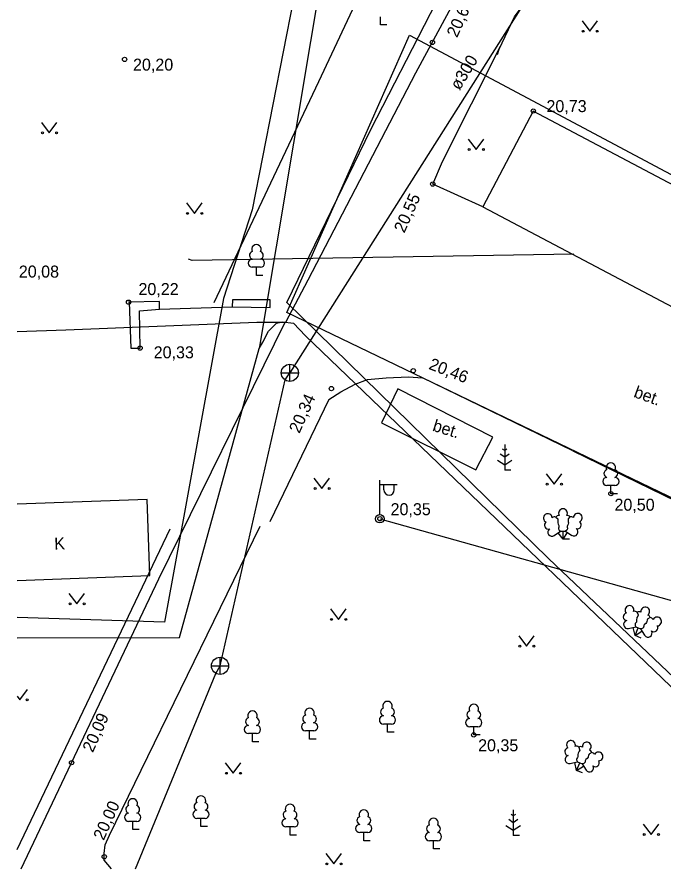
# Model space of a CAD drawing. Extents: x 714038 to 714279, y 6589845 to 6590041.
# Drawn here: x 714037.81 to 714075.51, y 6589845.18 to 6589894.87 of the extents above; entities that cross this region are included whole.
import ezdxf

# ---------------------------------------------------------------- set-up
doc = ezdxf.new("R2010")
doc.units = 0
for name, color, linetype in [('AED', 7, 'Continuous'), ('HALJASTUS', 7, 'Continuous'), ('HOONE', 7, 'Continuous'), ('HOONEDET', 7, 'Continuous'), ('KKAEV', 7, 'Continuous'), ('KORGUS', 7, 'Continuous'), ('MPKAABEL', 7, 'Continuous'), ('POST', 7, 'Continuous'), ('PUU', 7, 'Continuous'), ('SITRASS', 7, 'Continuous'), ('SKTRASS', 7, 'Continuous'), ('TEE', 7, 'Continuous'), ('TORU NR', 7, 'Continuous'), ('Слой 1', 7, 'Continuous')]:
    doc.layers.add(name, color=color, linetype=linetype)

msp = doc.modelspace()

# ---------------------------------------------------------------- linework, layer by layer
at = {"layer": 'AED'}
for points in [[(714049.29, 6589878.22), (714055.4, 6589891.11), (714061.33, 6589903.75), (714049.58, 6589910.2), (714039.2, 6589915.93), (714037.81, 6589916.678)], [(714044.34, 6589878.24), (714044.45, 6589875.56), (714044.98, 6589875.56), (714044.95, 6589877.74), (714046.12, 6589877.83), (714046.12, 6589878.27), (714044.31, 6589878.24)], [(714050.37, 6589878.38), (714050.34, 6589877.97), (714052.56, 6589877.92), (714052.56, 6589878.38), (714050.37, 6589878.38)], [(714046.12, 6589877.83), (714050.34, 6589877.97)]]:
    msp.add_lwpolyline(points, dxfattribs=at)
at = {"layer": 'HALJASTUS'}
for p, q in [((714070.737, 6589894.647), (714071.2, 6589894.04)), ((714071.2, 6589894.04), (714071.646, 6589894.647)), ((714039.227, 6589888.727), (714039.69, 6589888.12)), ((714039.69, 6589888.12), (714040.136, 6589888.727)), ((714064.097, 6589887.757), (714064.56, 6589887.15)), ((714064.56, 6589887.15), (714065.006, 6589887.757)), ((714047.687, 6589884.027), (714048.15, 6589883.42)), ((714048.15, 6589883.42), (714048.596, 6589884.027)), ((714068.647, 6589868.227), (714069.11, 6589867.62)), ((714069.11, 6589867.62), (714069.556, 6589868.227)), ((714055.117, 6589867.977), (714055.58, 6589867.37)), ((714055.58, 6589867.37), (714056.026, 6589867.977)), ((714040.837, 6589861.247), (714041.3, 6589860.64)), ((714041.3, 6589860.64), (714041.746, 6589861.247)), ((714056.077, 6589860.347), (714056.54, 6589859.74)), ((714056.54, 6589859.74), (714056.986, 6589860.347)), ((714067.047, 6589858.777), (714067.51, 6589858.17)), ((714067.51, 6589858.17), (714067.956, 6589858.777)), ((714037.97, 6589855.05), (714038.416, 6589855.657)), ((714037.81, 6589855.259), (714037.97, 6589855.05)), ((714049.947, 6589851.367), (714050.41, 6589850.76)), ((714050.41, 6589850.76), (714050.856, 6589851.367)), ((714074.307, 6589847.797), (714074.77, 6589847.19)), ((714074.77, 6589847.19), (714075.216, 6589847.797)), ((714055.807, 6589846.077), (714056.27, 6589845.47)), ((714056.27, 6589845.47), (714056.716, 6589846.077))]:
    msp.add_line(p, q, dxfattribs=at)
msp.add_lwpolyline([(714037.81, 6589846.322), (714046.74, 6589865.01)], dxfattribs=at)
for centre in [(714070.799, 6589894.04), (714071.628, 6589894.04), (714039.289, 6589888.12), (714040.118, 6589888.12), (714064.159, 6589887.15), (714064.988, 6589887.15), (714047.749, 6589883.42), (714048.578, 6589883.42), (714068.709, 6589867.62), (714069.538, 6589867.62), (714055.179, 6589867.37), (714056.008, 6589867.37), (714040.899, 6589860.64), (714041.728, 6589860.64), (714056.139, 6589859.74), (714056.968, 6589859.74), (714067.109, 6589858.17), (714067.938, 6589858.17), (714038.398, 6589855.05), (714050.009, 6589850.76), (714050.838, 6589850.76), (714074.369, 6589847.19), (714075.198, 6589847.19), (714055.869, 6589845.47), (714056.698, 6589845.47)]:
    msp.add_circle(centre, 0.055, dxfattribs=at)
at = {"layer": 'HOONE'}
for points in [[(714067.9, 6589889.39), (714064.95, 6589883.81), (714097.15, 6589866.78), (714100.1, 6589872.35), (714067.9, 6589889.39)], [(714037.81, 6589862.015), (714045.54, 6589862.29), (714045.39, 6589866.73), (714037.81, 6589866.46)]]:
    msp.add_lwpolyline(points, dxfattribs=at)
at = {"layer": 'HOONEDET'}
msp.add_lwpolyline([(714060, 6589873.19), (714059.06, 6589871.21), (714064.55, 6589868.47), (714065.54, 6589870.36), (714060, 6589873.19)], dxfattribs=at)
at = {"layer": 'KKAEV'}
for p, q in [((714053.71, 6589873.62), (714053.71, 6589874.62)), ((714053.21, 6589874.12), (714054.21, 6589874.12)), ((714049.64, 6589856.53), (714049.64, 6589857.53)), ((714049.14, 6589857.03), (714050.14, 6589857.03))]:
    msp.add_line(p, q, dxfattribs=at)
for centre in [(714053.71, 6589874.12), (714049.64, 6589857.03)]:
    msp.add_circle(centre, 0.5, dxfattribs=at)
at = {"layer": 'KORGUS'}
for centre in [(714062.02, 6589893.39), (714044.08, 6589892.4), (714067.9, 6589889.39), (714062.04, 6589885.13), (714044.31, 6589878.24), (714044.98, 6589875.56), (714060.9, 6589874.24), (714056.13, 6589873.2), (714072.42, 6589867.07), (714058.96, 6589865.61), (714064.43, 6589853), (714040.99, 6589851.38), (714042.89, 6589845.89)]:
    msp.add_circle(centre, 0.125, dxfattribs=at)
at = {"layer": 'MPKAABEL'}
for points in [[(714053.53, 6589878.23), (714058.43, 6589888.31), (714065.38, 6589901.86), (714065.06, 6589912.86)], [(714070.26, 6589881.04), (714048.02, 6589880.67), (714047.81, 6589880.74)], [(714083.83, 6589848.69), (714083.41, 6589849.38), (714068.79, 6589863.28), (714053.53, 6589878.23)], [(714058.96, 6589865.61), (714093.643, 6589855.885), (714098.262, 6589854.503), (714102.429, 6589860.826)]]:
    msp.add_lwpolyline(points, dxfattribs=at)
at = {"layer": 'POST'}
for p, q in [((714058.96, 6589865.86), (714058.96, 6589867.86)), ((714058.96, 6589867.61), (714059.96, 6589867.61)), ((714059.187, 6589867.289), (714059.187, 6589867.61)), ((714059.799, 6589867.289), (714059.799, 6589867.61))]:
    msp.add_line(p, q, dxfattribs=at)
msp.add_circle((714058.96, 6589865.61), 0.25, dxfattribs=at)
msp.add_arc((714059.493, 6589867.289), 0.306, 180, 0, dxfattribs=at)
at = {"layer": 'PUU'}
for p, q in [((714058.99, 6589894.41), (714058.99, 6589894.885)), ((714059.37, 6589894.41), (714058.99, 6589894.41)), ((714052, 6589880.275), (714051.52, 6589880.275)), ((714051.76, 6589879.8), (714051.76, 6589880.275)), ((714052.14, 6589879.8), (714051.76, 6589879.8)), ((714066.23, 6589869.59), (714066.106, 6589869.673)), ((714066.23, 6589869.94), (714066.23, 6589868.44)), ((714066.354, 6589869.673), (714066.23, 6589869.59)), ((714066.23, 6589869.19), (714065.963, 6589869.368)), ((714066.497, 6589869.368), (714066.23, 6589869.19)), ((714065.806, 6589869.029), (714066.23, 6589868.747)), ((714066.23, 6589868.747), (714066.654, 6589869.029)), ((714066.59, 6589868.44), (714066.23, 6589868.44)), ((714072.66, 6589867.545), (714072.18, 6589867.545)), ((714072.42, 6589867.07), (714072.42, 6589867.545)), ((714072.8, 6589867.07), (714072.42, 6589867.07)), ((714069.12, 6589864.63), (714069.48, 6589864.885)), ((714069.63, 6589864.41), (714069.355, 6589864.795)), ((714069.48, 6589864.885), (714069.775, 6589864.885)), ((714069.63, 6589864.41), (714069.63, 6589864.885)), ((714069.63, 6589864.41), (714069.9, 6589864.8)), ((714069.775, 6589864.885), (714070.135, 6589864.64)), ((714070.01, 6589864.41), (714069.63, 6589864.41)), ((714073.447, 6589859.202), (714073.878, 6589859.296)), ((714073.83, 6589858.8), (714073.728, 6589859.262)), ((714073.83, 6589858.8), (714074.016, 6589859.237)), ((714073.878, 6589859.296), (714074.15, 6589859.18)), ((714074.15, 6589859.18), (714074.385, 6589858.813)), ((714073.83, 6589858.8), (714074.231, 6589859.053)), ((714074.18, 6589858.651), (714073.83, 6589858.8)), ((714055.1, 6589853.235), (714054.62, 6589853.235)), ((714054.86, 6589852.76), (714054.86, 6589853.235)), ((714059.64, 6589853.635), (714059.16, 6589853.635)), ((714059.4, 6589853.16), (714059.4, 6589853.635)), ((714059.78, 6589853.16), (714059.4, 6589853.16)), ((714064.67, 6589853.475), (714064.19, 6589853.475)), ((714064.43, 6589853), (714064.43, 6589853.475)), ((714051.77, 6589853.075), (714051.29, 6589853.075)), ((714051.53, 6589852.6), (714051.53, 6589853.075)), ((714055.24, 6589852.76), (714054.86, 6589852.76)), ((714064.81, 6589853), (714064.43, 6589853)), ((714051.91, 6589852.6), (714051.53, 6589852.6)), ((714070.037, 6589851.332), (714070.468, 6589851.426)), ((714070.42, 6589850.93), (714070.318, 6589851.392)), ((714070.42, 6589850.93), (714070.606, 6589851.367)), ((714070.42, 6589850.93), (714070.821, 6589851.183)), ((714070.468, 6589851.426), (714070.74, 6589851.31)), ((714070.74, 6589851.31), (714070.975, 6589850.943)), ((714070.77, 6589850.781), (714070.42, 6589850.93)), ((714066.73, 6589848.28), (714066.606, 6589848.363)), ((714066.73, 6589848.63), (714066.73, 6589847.13)), ((714066.854, 6589848.363), (714066.73, 6589848.28)), ((714044.79, 6589847.955), (714044.31, 6589847.955)), ((714044.55, 6589847.48), (714044.55, 6589847.955)), ((714048.77, 6589848.125), (714048.29, 6589848.125)), ((714048.53, 6589847.65), (714048.53, 6589848.125)), ((714066.306, 6589847.719), (714066.73, 6589847.437)), ((714066.73, 6589847.88), (714066.463, 6589848.058)), ((714066.997, 6589848.058), (714066.73, 6589847.88)), ((714066.73, 6589847.437), (714067.154, 6589847.719)), ((714044.93, 6589847.48), (714044.55, 6589847.48)), ((714048.91, 6589847.65), (714048.53, 6589847.65)), ((714053.96, 6589847.635), (714053.48, 6589847.635)), ((714053.72, 6589847.16), (714053.72, 6589847.635)), ((714058.26, 6589847.305), (714057.78, 6589847.305)), ((714058.02, 6589846.83), (714058.02, 6589847.305)), ((714054.1, 6589847.16), (714053.72, 6589847.16)), ((714058.4, 6589846.83), (714058.02, 6589846.83)), ((714062.32, 6589846.825), (714061.84, 6589846.825)), ((714062.08, 6589846.35), (714062.08, 6589846.825)), ((714067.09, 6589847.13), (714066.73, 6589847.13)), ((714062.46, 6589846.35), (714062.08, 6589846.35))]:
    msp.add_line(p, q, dxfattribs=at)
for points in [[(714069.217, 6589865.697), (714069.32, 6589865.595), (714069.335, 6589865.565), (714069.335, 6589865.51), (714069.32, 6589865.42), (714069.32, 6589865.375), (714069.34, 6589865.295), (714069.38, 6589865.205), (714069.39, 6589865.16), (714069.385, 6589865.115), (714069.37, 6589865.05), (714069.37, 6589865.02), (714069.39, 6589864.98), (714069.415, 6589864.95), (714069.48, 6589864.885)], [(714070.034, 6589865.711), (714069.94, 6589865.595), (714069.925, 6589865.565), (714069.925, 6589865.51), (714069.94, 6589865.42), (714069.945, 6589865.375), (714069.925, 6589865.295), (714069.885, 6589865.205), (714069.875, 6589865.16), (714069.88, 6589865.115), (714069.895, 6589865.05), (714069.895, 6589865.02), (714069.875, 6589864.98), (714069.85, 6589864.95), (714069.78, 6589864.885)], [(714073.956, 6589860.146), (714074.01, 6589860.012), (714074.012, 6589859.978), (714073.99, 6589859.928), (714073.941, 6589859.851), (714073.924, 6589859.809), (714073.911, 6589859.728), (714073.912, 6589859.629), (714073.904, 6589859.584), (714073.881, 6589859.545), (714073.842, 6589859.491), (714073.83, 6589859.463), (714073.833, 6589859.418), (714073.844, 6589859.381), (714073.878, 6589859.296)], [(714074.712, 6589859.839), (714074.58, 6589859.768), (714074.555, 6589859.747), (714074.533, 6589859.696), (714074.511, 6589859.607), (714074.498, 6589859.564), (714074.449, 6589859.498), (714074.376, 6589859.431), (714074.35, 6589859.394), (714074.337, 6589859.35), (714074.325, 6589859.285), (714074.313, 6589859.257), (714074.279, 6589859.228), (714074.244, 6589859.21), (714074.154, 6589859.178)], [(714070.546, 6589852.276), (714070.6, 6589852.142), (714070.602, 6589852.108), (714070.58, 6589852.058), (714070.531, 6589851.981), (714070.514, 6589851.939), (714070.501, 6589851.858), (714070.502, 6589851.759), (714070.494, 6589851.714), (714070.471, 6589851.675), (714070.432, 6589851.621), (714070.42, 6589851.593), (714070.423, 6589851.548), (714070.434, 6589851.511), (714070.468, 6589851.426)], [(714071.302, 6589851.969), (714071.17, 6589851.898), (714071.145, 6589851.877), (714071.123, 6589851.826), (714071.101, 6589851.737), (714071.088, 6589851.694), (714071.039, 6589851.628), (714070.966, 6589851.561), (714070.94, 6589851.524), (714070.927, 6589851.48), (714070.915, 6589851.415), (714070.903, 6589851.387), (714070.869, 6589851.358), (714070.834, 6589851.34), (714070.744, 6589851.308)]]:
    msp.add_lwpolyline(points, dxfattribs=at)
for centre, radius, start, end in [((714051.76, 6589881.32), 0.277, 332.5799, 207.4201), ((714051.59, 6589880.973), 0.233, 109.0217, 253.1415), ((714051.93, 6589880.973), 0.233, 286.8508, 70.9859), ((714051.523, 6589880.512), 0.238, 90.0016, 269.3953), ((714051.997, 6589880.512), 0.238, 270.6047, 89.9984), ((714072.42, 6589868.59), 0.277, 332.5799, 207.4201), ((714072.25, 6589868.243), 0.233, 109.0217, 253.1415), ((714072.59, 6589868.243), 0.233, 286.8508, 70.9859), ((714072.183, 6589867.782), 0.238, 90.0016, 269.3953), ((714072.657, 6589867.782), 0.238, 270.6047, 89.9984), ((714069.63, 6589865.93), 0.256, 90.0013, 211.0159), ((714069.63, 6589865.93), 0.256, 328.9841, 89.9987), ((714068.747, 6589865.647), 0.256, 125.5389, 246.5536), ((714068.747, 6589865.647), 0.256, 4.5218, 125.5364), ((714069.133, 6589865.514), 0.202, 65.2382, 130.7412), ((714069.392, 6589865.598), 0.202, 84.7965, 150.2995), ((714069.868, 6589865.598), 0.202, 34.3857, 95.2035), ((714070.106, 6589865.523), 0.202, 50.3173, 111.1351), ((714070.49, 6589865.663), 0.256, 55.522, 176.5367), ((714070.49, 6589865.663), 0.256, 294.5049, 55.5195), ((714068.775, 6589865.23), 0.224, 125.4667, 288.5349), ((714070.47, 6589865.245), 0.224, 252.5235, 55.5918), ((714068.984, 6589864.824), 0.237, 125.5377, 305.5366), ((714070.268, 6589864.836), 0.237, 235.5219, 55.5208), ((714073.365, 6589859.89), 0.224, 102.3637, 265.432), ((714073.503, 6589860.284), 0.256, 102.436, 223.4506), ((714073.503, 6589860.284), 0.256, 341.4189, 102.4335), ((714073.806, 6589860.011), 0.202, 42.1353, 107.6383), ((714074.078, 6589859.985), 0.202, 61.6935, 127.1965), ((714074.426, 6589860.198), 0.256, 66.8983, 187.9129), ((714074.426, 6589860.198), 0.256, 305.8812, 66.8958), ((714073.398, 6589859.434), 0.237, 102.4347, 282.4337), ((714074.514, 6589859.799), 0.202, 11.2827, 72.1006), ((714074.705, 6589859.637), 0.202, 27.2143, 88.0322), ((714075.113, 6589859.615), 0.256, 32.4191, 153.4337), ((714075.113, 6589859.615), 0.256, 271.402, 32.4166), ((714074.93, 6589859.239), 0.224, 229.4206, 32.4889), ((714074.584, 6589858.941), 0.237, 212.4189, 32.4178), ((714059.4, 6589854.68), 0.277, 332.5799, 207.4201), ((714064.43, 6589854.52), 0.277, 332.5799, 207.4201), ((714051.53, 6589854.12), 0.277, 332.5799, 207.4201), ((714054.69, 6589853.933), 0.233, 109.0217, 253.1415), ((714054.86, 6589854.28), 0.277, 332.5799, 207.4201), ((714055.03, 6589853.933), 0.233, 286.8508, 70.9859), ((714059.23, 6589854.333), 0.233, 109.0217, 253.1415), ((714059.57, 6589854.333), 0.233, 286.8508, 70.9859), ((714064.26, 6589854.173), 0.233, 109.0217, 253.1415), ((714064.6, 6589854.173), 0.233, 286.8508, 70.9859), ((714051.36, 6589853.773), 0.233, 109.0217, 253.1415), ((714051.7, 6589853.773), 0.233, 286.8508, 70.9859), ((714054.623, 6589853.472), 0.238, 90.0016, 269.3953), ((714055.097, 6589853.472), 0.238, 270.6047, 89.9984), ((714059.163, 6589853.872), 0.238, 90.0016, 269.3953), ((714059.637, 6589853.872), 0.238, 270.6047, 89.9984), ((714064.193, 6589853.712), 0.238, 90.0016, 269.3953), ((714064.667, 6589853.712), 0.238, 270.6047, 89.9984), ((714051.293, 6589853.312), 0.238, 90.0016, 269.3953), ((714051.767, 6589853.312), 0.238, 270.6047, 89.9984), ((714070.093, 6589852.414), 0.256, 102.436, 223.4506), ((714070.093, 6589852.414), 0.256, 341.4189, 102.4335), ((714069.955, 6589852.02), 0.224, 102.3637, 265.432), ((714070.396, 6589852.141), 0.202, 42.1353, 107.6383), ((714070.668, 6589852.115), 0.202, 61.6935, 127.1965), ((714071.016, 6589852.328), 0.256, 66.8983, 187.9129), ((714071.016, 6589852.328), 0.256, 305.8812, 66.8958), ((714069.988, 6589851.564), 0.237, 102.4347, 282.4337), ((714071.104, 6589851.929), 0.202, 11.2827, 72.1006), ((714071.295, 6589851.767), 0.202, 27.2143, 88.0322), ((714071.703, 6589851.745), 0.256, 32.4191, 153.4337), ((714071.703, 6589851.745), 0.256, 271.402, 32.4166), ((714071.174, 6589851.071), 0.237, 212.4189, 32.4178), ((714071.52, 6589851.369), 0.224, 229.4206, 32.4889), ((714044.55, 6589849), 0.277, 332.5799, 207.4201), ((714048.53, 6589849.17), 0.277, 332.5799, 207.4201), ((714044.38, 6589848.653), 0.233, 109.0217, 253.1415), ((714044.72, 6589848.653), 0.233, 286.8508, 70.9859), ((714048.36, 6589848.823), 0.233, 109.0217, 253.1415), ((714048.7, 6589848.823), 0.233, 286.8508, 70.9859), ((714053.72, 6589848.68), 0.277, 332.5799, 207.4201), ((714044.313, 6589848.192), 0.238, 90.0016, 269.3953), ((714044.787, 6589848.192), 0.238, 270.6047, 89.9984), ((714048.293, 6589848.362), 0.238, 90.0016, 269.3953), ((714048.767, 6589848.362), 0.238, 270.6047, 89.9984), ((714053.55, 6589848.333), 0.233, 109.0217, 253.1415), ((714053.89, 6589848.333), 0.233, 286.8508, 70.9859), ((714057.85, 6589848.003), 0.233, 109.0217, 253.1415), ((714058.02, 6589848.35), 0.277, 332.5799, 207.4201), ((714058.19, 6589848.003), 0.233, 286.8508, 70.9859), ((714053.483, 6589847.872), 0.238, 90.0016, 269.3953), ((714053.957, 6589847.872), 0.238, 270.6047, 89.9984), ((714057.783, 6589847.542), 0.238, 90.0016, 269.3953), ((714058.257, 6589847.542), 0.238, 270.6047, 89.9984), ((714061.91, 6589847.523), 0.233, 109.0217, 253.1415), ((714062.08, 6589847.87), 0.277, 332.5799, 207.4201), ((714062.25, 6589847.523), 0.233, 286.8508, 70.9859), ((714061.843, 6589847.062), 0.238, 90.0016, 269.3953), ((714062.317, 6589847.062), 0.238, 270.6047, 89.9984)]:
    msp.add_arc(centre, radius, start, end, dxfattribs=at)
at = {"layer": 'SITRASS'}
for points in [[(714059.07, 6589920.38), (714053.93, 6589895.94), (714051.52, 6589883.63), (714049.85, 6589878.45), (714046.4, 6589859.57), (714037.81, 6589859.852)], [(714059.38, 6589920.22), (714056.91, 6589905.45), (714051.92, 6589875.53)], [(714051.92, 6589875.53), (714052.13, 6589875.9), (714052.47, 6589876.55), (714052.93, 6589877.01), (714053.29, 6589877.1), (714053.93, 6589877.01), (714054.62, 6589876.27), (714083.17, 6589848.87)], [(714037.81, 6589858.671), (714047.27, 6589858.69), (714051.92, 6589875.53)]]:
    msp.add_lwpolyline(points, dxfattribs=at)
at = {"layer": 'SKTRASS'}
for points in [[(714073.33, 6589905.13), (714053.71, 6589874.12)], [(714049.64, 6589857.03), (714053.43, 6589873.71), (714053.71, 6589874.12)], [(714044.715, 6589845.18), (714049.4, 6589856.59), (714049.64, 6589857.03)]]:
    msp.add_lwpolyline(points, dxfattribs=at)
at = {"layer": 'TEE'}
for points in [[(714037.81, 6589876.526), (714040.66, 6589876.63), (714051.78, 6589877.08), (714053.47, 6589877.08), (714054.77, 6589879.55), (714061.06, 6589891.61), (714065.07, 6589899.08), (714066.22, 6589901.9), (714066.36, 6589903.3), (714066.15, 6589904.44), (714065.78, 6589905.05), (714065.33, 6589905.43), (714063.27, 6589906.66), (714062.32, 6589907.21)], [(714065.81, 6589892.68), (714065.91, 6589892.99), (714066.8, 6589894.88), (714067.93, 6589896.42), (714074.55, 6589899.06), (714077.84, 6589899.91), (714078.73, 6589900.12), (714079.21, 6589899.98), (714079.82, 6589899.67), (714081.84, 6589898.71)], [(714064.95, 6589883.81), (714062.04, 6589885.13), (714062.61, 6589886.44), (714065.99, 6589893.17)], [(714038.042, 6589845.18), (714046.08, 6589862.1), (714053.43, 6589877.08)], [(714055.98, 6589872.569), (714056.687, 6589873.017), (714057.522, 6589873.458), (714058.238, 6589873.726), (714059.314, 6589873.833), (714060.628, 6589873.89), (714061.448, 6589873.832)], [(714070.204, 6589869.569), (714061.448, 6589873.832)], [(714055.98, 6589872.569), (714052.548, 6589865.42)], [(714070.204, 6589869.569), (714084.491, 6589862.601)], [(714043.309, 6589845.18), (714042.89, 6589845.7), (714042.89, 6589846.08), (714042.95, 6589846.58), (714043.2, 6589847.15), (714045.04, 6589850.95), (714051.984, 6589865.183)]]:
    msp.add_lwpolyline(points, dxfattribs=at)
at = {"layer": 'Слой 1'}
msp.add_lwpolyline([(714102.17, 6589871.7), (714094.32, 6589857.99), (714053.54, 6589877.63), (714060.68, 6589893.81)], close=True, dxfattribs=at)

# ---------------------------------------------------------------- texts
at = {"layer": 'HOONE'}
msp.add_text('K', height=0.7, rotation=1.7209, dxfattribs=at).set_placement((714039.987, 6589863.809))
at = {"layer": 'KORGUS'}
for s, rotation, p in [('20,68', 65.8483, (714063.455, 6589893.631)), ('20,55', 65.8483, (714060.382, 6589882.237)), ('20,46', 338.5527, (714061.756, 6589874.359)), ('20,34', 65.8483, (714054.265, 6589870.548)), ('20,09', 65.8483, (714042.225, 6589851.931)), ('20,00', 65.8483, (714042.859, 6589846.807))]:
    msp.add_text(s, height=0.7, rotation=rotation, dxfattribs=at).set_placement(p)
for s, p in [('20,20', (714044.569, 6589891.745)), ('20,73', (714068.664, 6589889.325)), ('20,08', (714037.914, 6589879.675)), ('20,22', (714044.886, 6589878.655)), ('20,33', (714045.774, 6589874.965)), ('20,50', (714072.629, 6589866.075)), ('20,35', (714059.581, 6589865.815)), ('20,35', (714064.681, 6589852.045))]:
    msp.add_text(s, height=0.7, dxfattribs=at).set_placement(p)
at = {"layer": 'TEE'}
for rotation, p in [(340.1849, (714073.702, 6589872.721)), (342.7592, (714061.982, 6589870.752))]:
    msp.add_text('bet.', height=0.7, rotation=rotation, dxfattribs=at).set_placement(p)
at = {"layer": 'TORU NR'}
msp.add_text('ø300', height=0.7, rotation=58.7707, dxfattribs=at).set_placement((714063.596, 6589890.555))

doc.saveas('drawing.dxf')
